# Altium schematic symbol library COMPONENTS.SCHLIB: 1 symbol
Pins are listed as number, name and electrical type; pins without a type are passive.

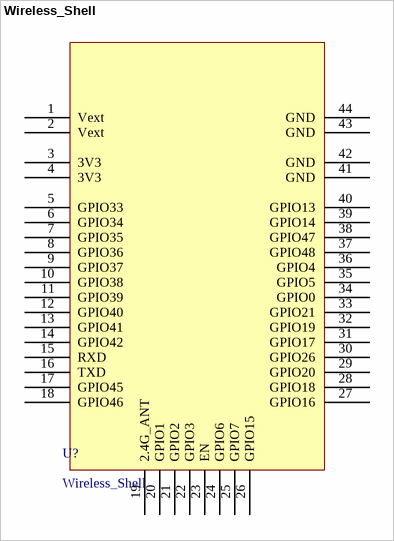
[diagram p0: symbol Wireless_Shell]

## Wireless_Shell
designator U?
footprint Esp_PICO
pins: 1 Vext, 2 Vext, 3 3V3, 4 3V3, 5 GPIO33, 6 GPIO34, 7 GPIO35, 8 GPIO36, 9 GPIO37, 10 GPIO38, 11 GPIO39, 12 GPIO40, 13 GPIO41, 14 GPIO42, 15 RXD, 16 TXD, 17 GPIO45, 18 GPIO46, 19 2.4G_ANT, 20 GPIO1, 21 GPIO2, 22 GPIO3, 23 EN, 24 GPIO6, 25 GPIO7, 26 GPIO15, 27 GPIO16, 28 GPIO18, 29 GPIO20, 30 GPIO26, 31 GPIO17, 32 GPIO19, 33 GPIO21, 34 GPIO0, 35 GPIO5, 36 GPIO4, 37 GPIO48, 38 GPIO47, 39 GPIO14, 40 GPIO13, 41 GND, 42 GND, 43 GND, 44 GND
